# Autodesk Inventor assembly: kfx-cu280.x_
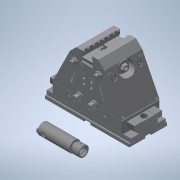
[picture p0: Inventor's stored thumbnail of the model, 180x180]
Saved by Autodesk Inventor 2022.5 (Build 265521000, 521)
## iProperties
Created: 2021-10
Part Number: kfx-cu280.x_
Material: 一般
Document SubType Name: Assembly
Designer: ImaoCorp
Sending System: SOLIDWORKS 2019-2019304
MC: AMD64
MC_MODEL: Intel64 Family 6 Model 60 Stepping 3, GenuineIntel
OS: Windows_NT
FRU: Parasolid Version 31.0, build 290,  9- 1-2019
FORMAT: text
GUISE: transmit
KEY: kfx-cu280
FILE: kfx-cu280.x_t
DATE: Thu Oct 14 10:04:24 2021
Author: ImaoCorp
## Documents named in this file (7)
- X:\14_SW2022-Inv2022\00_全2023-1023新製品(TCC)まで\k\kfx-cu280\KFX-CU280.iam
- X:\14_SW2022-Inv2022\00_全2023-1023新製品(TCC)まで\k\kfx-cu280\kfx-cu280_01.ipt
- X:\14_SW2022-Inv2022\00_全2023-1023新製品(TCC)まで\k\kfx-cu280\kfx-cu280_02.ipt
- X:\14_SW2022-Inv2022\00_全2023-1023新製品(TCC)まで\k\kfx-cu280\kfx-cu280_03.ipt
- X:\14_SW2022-Inv2022\00_全2023-1023新製品(TCC)まで\k\kfx-cu280\kfx-cu280_04.ipt
- X:\14_SW2022-Inv2022\00_全2023-1023新製品(TCC)まで\k\kfx-cu280\kfx-cu280_05.ipt
- X:\14_SW2022-Inv2022\00_全2023-1023新製品(TCC)まで\k\kfx-cu280\kfx-cu280_06.ipt
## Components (6 placed, 6 different names)
1. kfx-cu280_01
2. kfx-cu280_02
3. kfx-cu280_03
4. kfx-cu280_04
5. kfx-cu280_05
6. kfx-cu280_06
